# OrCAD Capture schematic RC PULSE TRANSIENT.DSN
size A
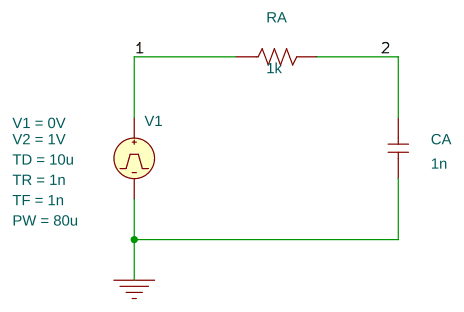
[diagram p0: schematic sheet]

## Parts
CA  1n  [RAD/CK05]
RA  1k  [AX/RC05]
V1  VPULSE

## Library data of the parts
CA = C
RA = R
V1 = VPULSE: PW: 80u; TD: 10u; TF: 1n; TR: 1n; V1: 0V; V2: 1V

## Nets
0: CA.1 V1.2(-)
1: RA.1 V1.1(+)
2: CA.2 RA.2
